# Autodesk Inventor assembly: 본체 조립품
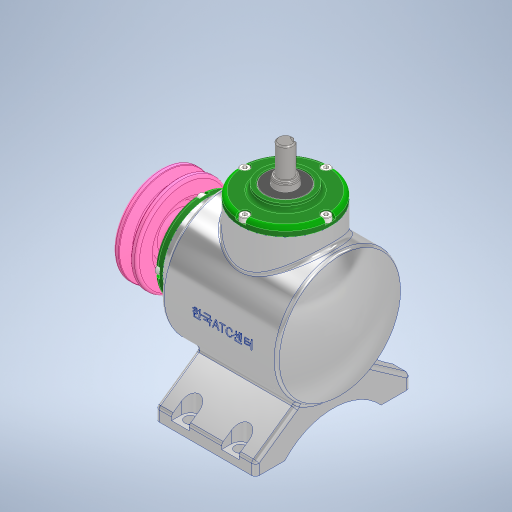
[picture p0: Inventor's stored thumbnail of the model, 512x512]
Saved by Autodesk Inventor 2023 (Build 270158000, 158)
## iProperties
Created: 2023-12
Part Number: 본체 조립품
Document SubType Name: Assembly
Designer: asung
Author: asung
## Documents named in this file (17)
- C:\Users\asung\Desktop\731210V1006\본체 조립품.iam
- C:\Users\asung\Desktop\731210V1006\본체.ipt
- C:\Users\asung\Desktop\731210V1006\커버.ipt
- C:\Users\asung\Desktop\731210V1006\베어링 6203.ipt
- C:\Users\asung\Desktop\731210V1006\오일실 17 x 32 x 8.ipt
- C:\Users\asung\Desktop\731210V1006\메인 축.ipt
- 메인 축.ipt
- C:\Users\asung\Desktop\731210V1006\키 5 x 5 x 14.ipt
- C:\Users\asung\Desktop\731210V1006\메인 베벨기어.ipt
- C:\Users\asung\Desktop\731210V1006\서브 축.ipt
- 서브 축.ipt
- C:\Users\asung\Desktop\731210V1006\키 4 x 4 x 14.ipt
- C:\Users\asung\Desktop\731210V1006\서브 베벨기어.ipt
- C:\Users\asung\Desktop\731210V1006\V-벨트풀리.ipt
- C:\Users\asung\Desktop\731210V1006\볼트 M4 x 10.ipt
- C:\Users\asung\Desktop\731210V1006\와셔 4 x 16.ipt
- C:\Users\asung\Desktop\731210V1006\육각볼트 M4 x 8.ipt
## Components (1 placed, 1 different names)
1. V-벨트풀리:1
